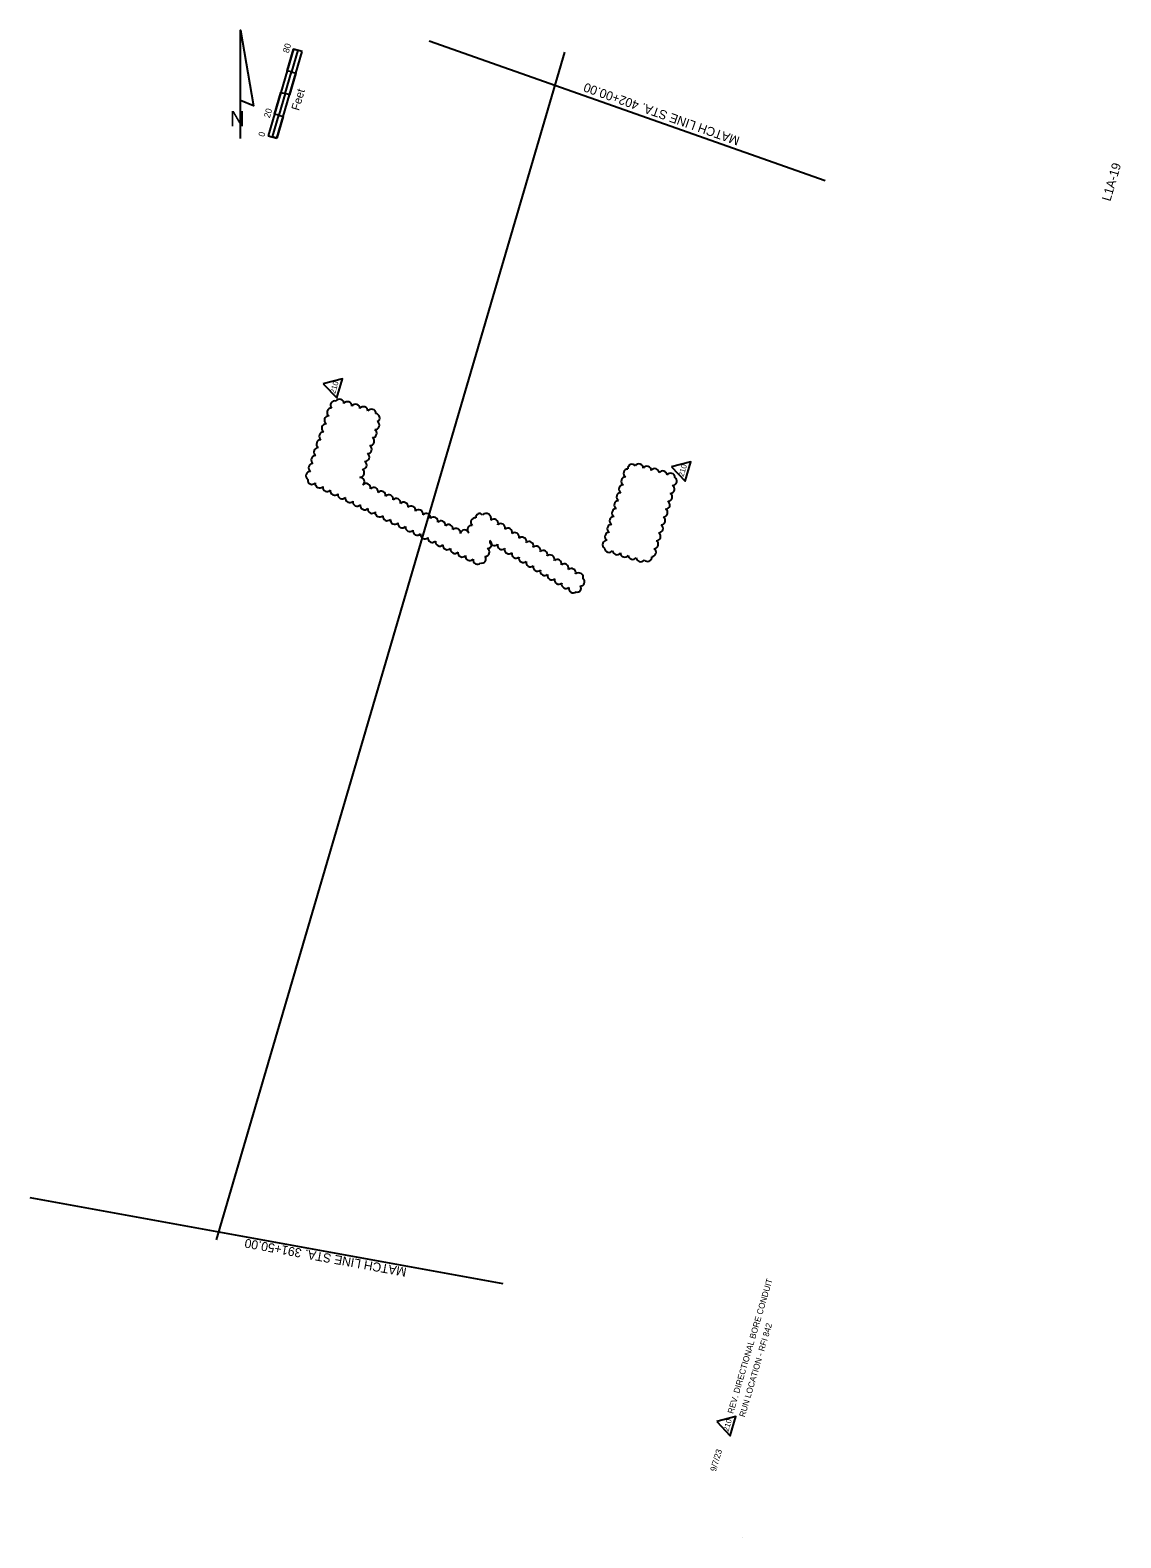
# Model space of a CAD drawing. Extents: x 929455 to 930421, y 615204 to 616540.
import ezdxf

# ---------------------------------------------------------------- set-up
doc = ezdxf.new("R2010")
doc.units = 0
for name, color, linetype in [('ActivePointCell_dp', 7, 'Continuous'), ('AdhocPoint_dp', 7, 'Continuous'), ('Cloud_dp', 7, 'Continuous'), ('MatchLines_dp', 7, 'Continuous'), ('NorthArw_dp', 7, 'Continuous'), ('Scale_dp', 7, 'Continuous'), ('TextMinor', 7, 'Continuous'), ('TextShtNo', 7, 'Continuous')]:
    doc.layers.add(name, color=color, linetype=linetype)

msp = doc.modelspace()

# ---------------------------------------------------------------- linework, layer by layer
at = {"layer": 'ActivePointCell_dp'}
msp.add_line((929620, 615467.9), (929928.5, 616520.5), dxfattribs=at)
at = {"layer": 'AdhocPoint_dp'}
msp.add_line((930086.1, 615203.7), (930086.1, 615203.7), dxfattribs=at)
at = {"layer": 'Cloud_dp'}
for points in [[(929714.6, 616226.4), (929726.6, 616213.9), (929731.6, 616230.9)], [(930023.2, 616152.8), (930035.2, 616140.3), (930040.2, 616157.3)], [(930063.1, 615306.7), (930075.1, 615294.2), (930080, 615311.2)]]:
    msp.add_lwpolyline(points, close=True, dxfattribs=at)
for centre, radius, start, end in [((929724.8, 616207.4), 3.89, 74.3811, 219.3811), ((929729, 616208.9), 3.87, 0.0636, 145.0636), ((929736.1, 616206.7), 3.88, 0.0636, 145.0636), ((929743.2, 616204.5), 3.88, 0.0636, 145.0636), ((929750.2, 616202.3), 3.88, 0.0636, 145.0636), ((929719.4, 616194.1), 3.88, 89.0887, 234.0887), ((929721.8, 616201.1), 3.88, 89.0887, 234.0887), ((929757.3, 616200.1), 3.88, 0.0636, 145.0636), ((929760.3, 616189.8), 3.96, 270.0636, 55.0636), ((929760.8, 616196.3), 3.77, 299.1576, 84.1576), ((929714.8, 616180), 3.88, 89.0887, 234.0887), ((929717.1, 616187), 3.88, 89.0887, 234.0887), ((929758.1, 616182.6), 3.88, 270.0636, 55.0636), ((929710.1, 616166), 3.88, 89.0887, 234.0887), ((929712.4, 616173), 3.88, 89.0887, 234.0887), ((929753.7, 616168.5), 3.88, 270.0636, 55.0636), ((929755.9, 616175.6), 3.88, 270.0636, 55.0636), ((929705.4, 616152), 3.88, 89.0887, 234.0887), ((929707.7, 616159), 3.88, 89.0887, 234.0887), ((929749.2, 616154.4), 3.88, 270.0636, 55.0636), ((929751.5, 616161.5), 3.88, 270.0636, 55.0636), ((929988.1, 616151.3), 3.83, 39.853, 184.853), ((929994.2, 616151.6), 3.83, 1.1658, 146.1658), ((930001.3, 616149.5), 3.83, 1.1658, 146.1658), ((929703.1, 616144.9), 3.88, 89.0887, 234.0887), ((929704.6, 616141.2), 3.88, 171.6735, 316.6735), ((929747, 616147.4), 3.88, 270.0636, 55.0636), ((929747.3, 616139.8), 3.73, 308.7045, 93.7045), ((929982.3, 616140.1), 3.83, 91.1658, 236.1658), ((929984.4, 616147.1), 3.83, 91.1658, 236.1658), ((930008.3, 616147.5), 3.83, 1.1658, 146.1658), ((930015.3, 616145.4), 3.83, 1.1658, 146.1658), ((930022.3, 616143.4), 3.83, 1.1658, 146.1658), ((930024, 616140.3), 3.83, 271.1658, 56.1658), ((929711.3, 616138), 3.88, 171.6735, 316.6735), ((929718, 616134.8), 3.88, 171.6735, 316.6735), ((929724.6, 616131.6), 3.88, 171.6735, 316.6735), ((929731.3, 616128.4), 3.88, 171.6735, 316.6735), ((929752.5, 616134), 4.06, 351.0819, 136.0819), ((929759.3, 616130.7), 3.88, 351.0819, 136.0819), ((929766, 616127.4), 3.88, 351.0819, 136.0819), ((929772.6, 616124.2), 3.88, 351.0819, 136.0819), ((929978.2, 616126.1), 3.83, 91.1658, 236.1658), ((929980.3, 616133.1), 3.83, 91.1658, 236.1658), ((930019.9, 616126.2), 3.83, 271.1658, 56.1658), ((930021.9, 616133.2), 3.83, 271.1658, 56.1658), ((929737.9, 616125.1), 3.88, 171.6735, 316.6735), ((929744.6, 616121.9), 3.88, 171.6735, 316.6735), ((929751.2, 616118.7), 3.88, 171.6735, 316.6735), ((929757.9, 616115.5), 3.88, 171.6735, 316.6735), ((929764.5, 616112.3), 3.88, 171.6735, 316.6735), ((929779.2, 616120.9), 3.88, 351.0819, 136.0819), ((929785.8, 616117.6), 3.88, 351.0819, 136.0819), ((929792.4, 616114.3), 3.88, 351.0819, 136.0819), ((929799.1, 616111), 3.88, 351.0819, 136.0819), ((929974.1, 616112), 3.83, 91.1658, 236.1658), ((929976.1, 616119), 3.83, 91.1658, 236.1658), ((930015.8, 616112.2), 3.83, 271.1658, 56.1658), ((930017.8, 616119.2), 3.83, 271.1658, 56.1658), ((929771.2, 616109), 3.88, 171.6735, 316.6735), ((929777.8, 616105.8), 3.88, 171.6735, 316.6735), ((929784.5, 616102.6), 3.88, 171.6735, 316.6735), ((929791.2, 616099.4), 3.88, 171.6735, 316.6735), ((929805.7, 616107.7), 3.88, 351.0819, 136.0819), ((929812.3, 616104.4), 3.88, 351.0819, 136.0819), ((929818.9, 616101.1), 3.88, 351.0819, 136.0819), ((929825.5, 616097.8), 3.88, 351.0819, 136.0819), ((929846, 616097.2), 3.82, 81.9568, 226.9568), ((929849.2, 616103.8), 3.88, 81.9568, 226.9568), ((929853.1, 616108.1), 3.34, 42.8809, 187.8809), ((929858.6, 616106.8), 4.71, 345.0811, 130.0811), ((929865.6, 616102.6), 3.88, 345.0811, 130.0811), ((929871.9, 616098.7), 3.88, 345.0811, 130.0811), ((929970, 616098), 3.83, 91.1658, 236.1658), ((929972, 616105), 3.83, 91.1658, 236.1658), ((930011.7, 616098.2), 3.83, 271.1658, 56.1658), ((930013.7, 616105.2), 3.83, 271.1658, 56.1658), ((929797.8, 616096.1), 3.88, 171.6735, 316.6735), ((929804.5, 616092.9), 3.88, 171.6735, 316.6735), ((929811.1, 616089.7), 3.88, 171.6735, 316.6735), ((929817.8, 616086.5), 3.88, 171.6735, 316.6735), ((929832.2, 616094.5), 3.88, 351.0819, 136.0819), ((929839.8, 616093), 3.91, 21.1703, 166.1703), ((929860, 616084.3), 3.81, 271.1658, 56.1658), ((929866, 616087), 3.99, 173.8836, 318.8836), ((929878.1, 616094.7), 3.88, 345.0811, 130.0811), ((929884.3, 616090.7), 3.88, 345.0811, 130.0811), ((929890.6, 616086.8), 3.88, 345.0811, 130.0811), ((929896.8, 616082.8), 3.88, 345.0811, 130.0811), ((929965.9, 616084), 3.83, 91.1658, 236.1658), ((929967.9, 616091), 3.83, 91.1658, 236.1658), ((930007.5, 616084.1), 3.83, 271.1658, 56.1658), ((930009.6, 616091.1), 3.83, 271.1658, 56.1658), ((929824.4, 616083.3), 3.88, 171.6735, 316.6735), ((929831.1, 616080), 3.88, 171.6735, 316.6735), ((929837.7, 616076.8), 3.88, 171.6735, 316.6735), ((929844.4, 616073.6), 3.88, 171.6735, 316.6735), ((929855, 616071.2), 3.66, 251.7413, 36.7413), ((929857.9, 616077.3), 3.88, 271.1658, 56.1658), ((929872.8, 616083.5), 3.88, 166.1387, 311.1387), ((929879.1, 616079.6), 3.88, 166.1387, 311.1387), ((929885.4, 616075.8), 3.88, 166.1387, 311.1387), ((929891.8, 616071.9), 3.88, 166.1387, 311.1387), ((929903.1, 616078.8), 3.88, 345.0811, 130.0811), ((929909.3, 616074.9), 3.88, 345.0811, 130.0811), ((929915.5, 616070.9), 3.88, 345.0811, 130.0811), ((929967.6, 616080.9), 3.83, 181.1658, 326.1658), ((929974.6, 616078.8), 3.83, 181.1658, 326.1658), ((929981.6, 616076.7), 3.83, 181.1658, 326.1658), ((929988.6, 616074.7), 3.83, 181.1658, 326.1658), ((929995.6, 616072.6), 3.83, 181.1658, 326.1658), ((930001.8, 616072.9), 3.83, 219.853, 4.853), ((930005.5, 616077.1), 3.83, 271.1658, 56.1658), ((929851.1, 616070.4), 3.88, 171.6735, 316.6735), ((929898.1, 616068.1), 3.88, 166.1387, 311.1387), ((929904.4, 616064.2), 3.88, 166.1387, 311.1387), ((929910.7, 616060.4), 3.88, 166.1387, 311.1387), ((929921.8, 616066.9), 3.88, 345.0811, 130.0811), ((929928, 616063), 3.88, 345.0811, 130.0811), ((929934.3, 616059), 3.88, 345.0811, 130.0811), ((929917, 616056.6), 3.88, 166.1387, 311.1387), ((929923.3, 616052.7), 3.88, 166.1387, 311.1387), ((929929.6, 616048.9), 3.88, 166.1387, 311.1387), ((929936, 616045), 3.88, 166.1387, 311.1387), ((929940.7, 616054.7), 4.23, 343.9181, 128.9181), ((929939.6, 616045.2), 3.34, 250.9317, 35.9317), ((929942.5, 616050.8), 3.57, 266.4342, 51.4342)]:
    msp.add_arc(centre, radius, start, end, dxfattribs=at)
at = {"layer": 'MatchLines_dp'}
for p, q in [((930159.3, 616406.3), (929808.5, 616530.2)), ((929873.8, 615428.8), (929454.9, 615505.1))]:
    msp.add_line(p, q, dxfattribs=at)
at = {"layer": 'NorthArw_dp'}
msp.add_line((929641.1, 616443.9), (929641.1, 616539.9), dxfattribs=at)
msp.add_lwpolyline([(929641.1, 616477.5), (929641.1, 616539.9), (929652.7, 616472.7)], close=True, dxfattribs=at)
at = {"layer": 'Scale_dp'}
for p, q in [((929688.2, 616523.1), (929665.8, 616446.3)), ((929673.5, 616444.1), (929695.9, 616520.9)), ((929695.9, 616520.9), (929688.2, 616523.1)), ((929665.8, 616446.3), (929673.5, 616444.1))]:
    msp.add_line(p, q, dxfattribs=at)
for points in [[(929686.5, 616502.8), (929682.6, 616503.9), (929688.2, 616523.1), (929692.1, 616522)], [(929684.7, 616482.5), (929680.8, 616483.6), (929686.5, 616502.8), (929690.3, 616501.7)], [(929675.2, 616464.4), (929671.4, 616465.5), (929677, 616484.7), (929680.8, 616483.6)], [(929673.5, 616444.1), (929669.6, 616445.2), (929675.2, 616464.4), (929679.1, 616463.3)]]:
    msp.add_lwpolyline(points, close=True, dxfattribs=at)

# ---------------------------------------------------------------- texts
at = {"layer": 'Cloud_dp'}
for p in [(929725.1, 616217.3), (930033.7, 616143.7), (930073.5, 615297.6)]:
    msp.add_text('210', height=4.8, rotation=73.6658, dxfattribs=at).set_placement(p)
at = {"layer": 'MatchLines_dp'}
for s, rotation, p in [('MATCH LINE STA. 402+00.00', 160.5475, (930084.1, 616445)), ('MATCH LINE STA. 391+50.00', 169.6711, (929788.8, 615442.9))]:
    msp.add_text(s, height=8, rotation=rotation, dxfattribs=at).set_placement(p)
at = {"layer": 'NorthArw_dp'}
msp.add_text('N', height=13.4, dxfattribs=at).set_placement((929632, 616454.7))
at = {"layer": 'Scale_dp'}
for s, height, p in [('80', 5.6, (929683.9, 616519.2)), ('Feet', 7.2, (929693, 616468.1)), ('20', 5.6, (929667.1, 616461.6)), ('0', 5.6, (929662.2, 616444.9))]:
    msp.add_text(s, height=height, rotation=73.7069, dxfattribs=at).set_placement(p)
at = {"layer": 'TextMinor'}
for s, height, p in [('REV. DIRECTIONAL BORE CONDUIT ', 5.376, (930077.7, 615313.3)), ('RUN LOCATION - RFI 842', 5.376, (930088, 615310.3)), ('9/7/23', 5.38, (930062.3, 615262.1))]:
    msp.add_text(s, height=height, rotation=73.6658, dxfattribs=at).set_placement(p)
at = {"layer": 'TextShtNo'}
msp.add_text('L1A-19', height=8, rotation=73.6658, dxfattribs=at).set_placement((930411.8, 616387.7))

doc.saveas('drawing.dxf')
